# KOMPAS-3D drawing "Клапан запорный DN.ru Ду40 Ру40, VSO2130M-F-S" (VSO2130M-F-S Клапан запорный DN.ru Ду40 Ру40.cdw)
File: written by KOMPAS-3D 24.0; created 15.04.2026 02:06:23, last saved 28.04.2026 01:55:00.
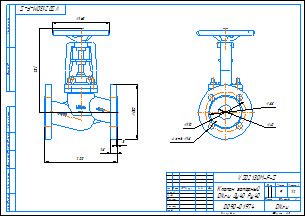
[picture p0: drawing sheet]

Document properties: Автор: DN.ru; Форматы листов документа: A3; Полное имя файла: VSO2130M-F-S Клапан запорный DN.ru Ду40 Ру40.m3d; Масса: 9; Наименование: Клапан запорный DN.ru Ду40 Ру40; Количество листов документа: 1; Примечание: D090-01974

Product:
- Part/product: Клапан запорный DN.ru Ду40 Ру40  | designation VSO2130M-F-S
    Масса: 9
    Раздел спецификации: Прочие изделия
    Примечание: D090-01974

Views: Вид 1, Вид:1, Проекционный вид 2
Referenced files in C:\Работа\VSO2130M-F-S Клапан запорный DN.ru\DN20\: VSO2130M-F-S DN20 PN40  Клапан запорный сильфонный DN.ru.m3d
Referenced files in C:\Работа\VSO2130M-F-S Клапан запорный DN.ru\DN40\: VSO2130M-F-S Клапан запорный DN.ru Ду40 Ру40.m3d
Referenced files in C:\Program Files\ASCON\KOMPAS-3D v24\Templates\: Чертеж_DN.ru.cdt
Referenced files in C:\Работа\ГОТОВЫЕ ИСХОДНИКИ\VSO2130M-F-S Клапан запорный сильфонный DN.ru Ду15-100 Ру40\DN40\: VSO2130M-F-S Клапан запорный DN.ru Ду40 Ру40.m3d
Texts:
  VSO2130M-F-S
  Чертеж_DN.ru.cdt
  Клапан запорный
  DN.ru Ду40 Ру40
  Клапан запорный DN.ru Ду40 Ру40
  VSO2130M-F-S  Клапан запорный DN.ru Ду40 Ру40
Dimensions and other numbers on the sheet: 0; 3; 2; 4; 150; 18; 231; 160; 200; 5; 40; 88; 110; 4 отв.; 1:2; 1; 9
